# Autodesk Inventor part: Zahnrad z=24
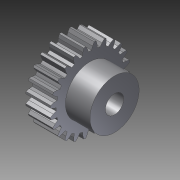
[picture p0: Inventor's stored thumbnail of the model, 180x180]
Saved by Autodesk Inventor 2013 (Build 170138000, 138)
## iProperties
Created: 2012-07
Part Number: Zahnrad z=24
Material: Stahl
Document SubType Name: Modeling
Designer: rYan
Mass: 4.63809 g
Surface Area: 6.6827 cm^2
Volume: 0.59084 cm^3
Density: 7.85 g/cm^3
Übersetzungsnorm: STEP AP214IS
Dateiname: c:/PPEXPORT/antriebselemente_und_normteile/stirnzahnraeder/stirnzahnraeder_stahl/modul_05_und_07/artikel_nr___21102400.stp
Postprozessor: Build: 138, Release: 2013 RTM - Date: Thu 03/01/2012
Gesendete Einheiten: Millimeter
Unbestimmtheit: 1.0000000000000002e-06
Author: rYan
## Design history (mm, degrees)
node "11"
node "1"
node "Basis1"
